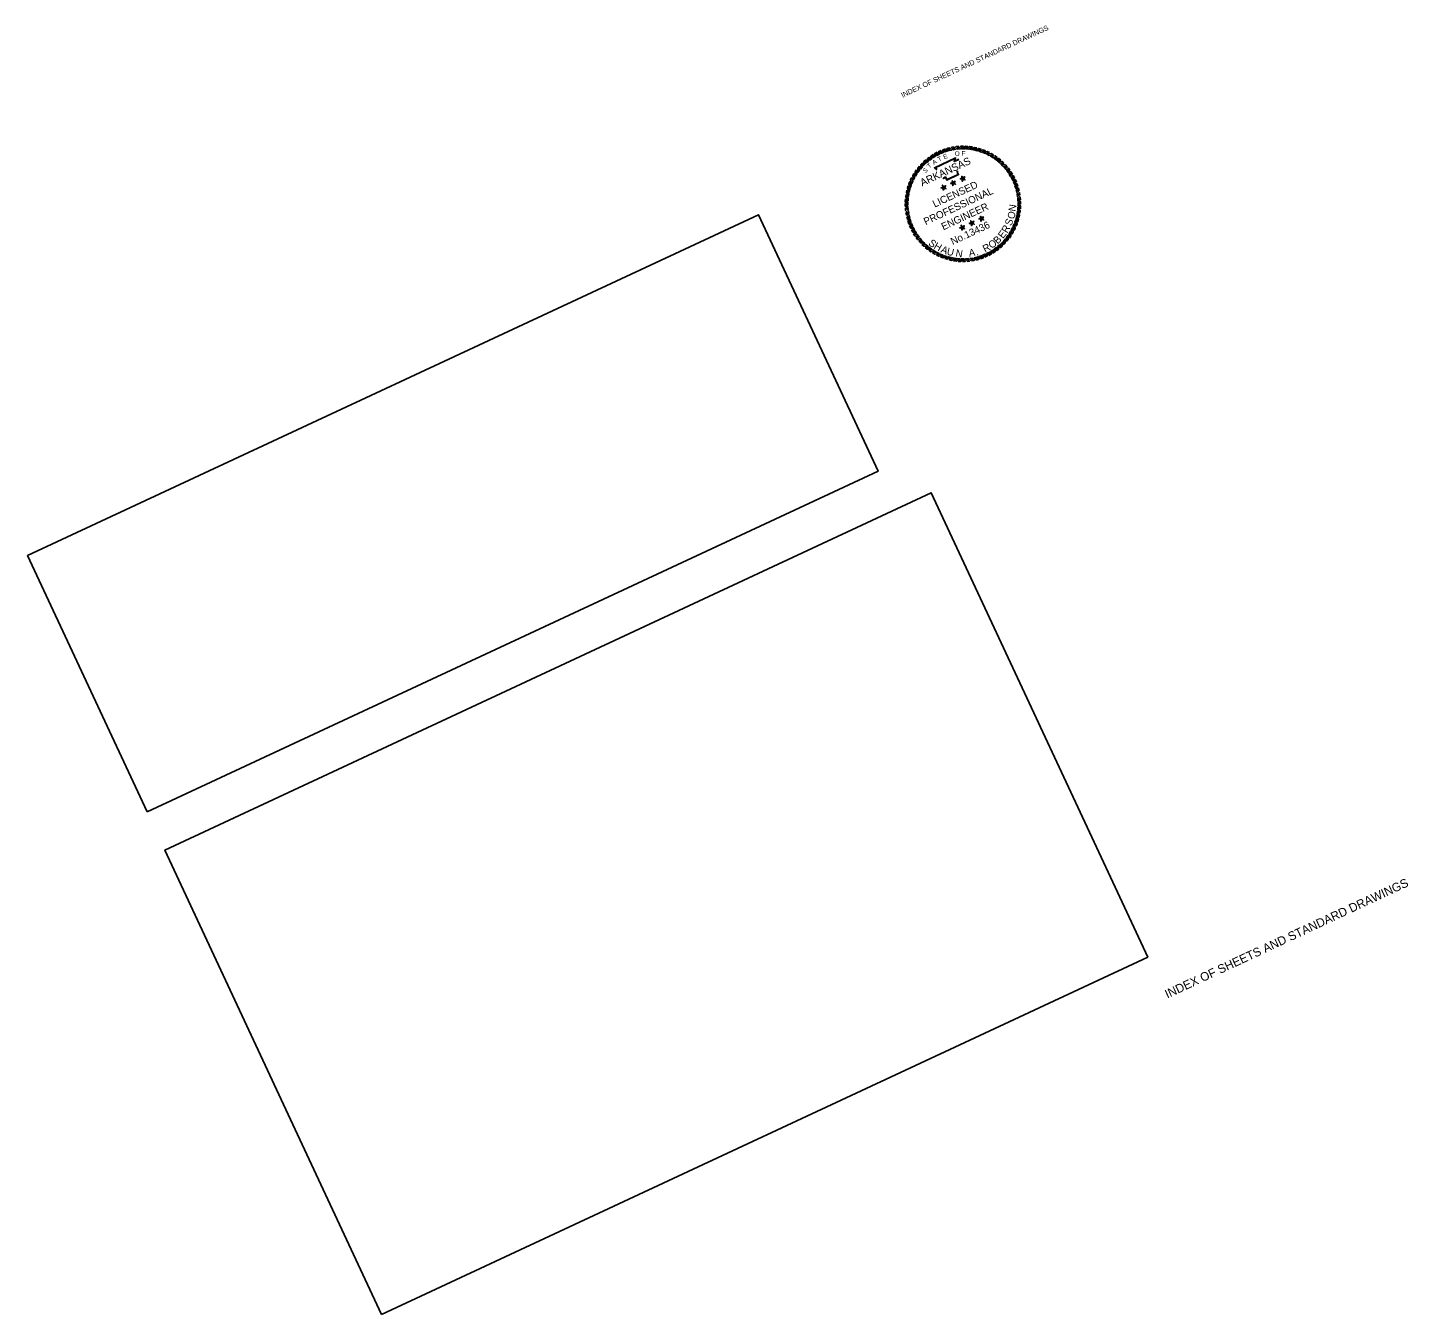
# Model space of a CAD drawing. Extents: x 757035 to 763666, y 1656342 to 1660766.
# Drawn here: x 757035 to 759892, y 1656342 to 1659005 of the extents above; entities that cross this region are included whole.
import ezdxf

# ---------------------------------------------------------------- set-up
doc = ezdxf.new("R2010")
doc.units = 0
for name, color, linetype in [('1', 7, 'Continuous'), ('60', 7, 'Continuous'), ('G-ANNO-SYMB', 7, 'Continuous')]:
    doc.layers.add(name, color=color, linetype=linetype)

msp = doc.modelspace()

# ---------------------------------------------------------------- linework, layer by layer
at = {"layer": '1'}
for points in [[(757282.5, 1657381.6), (758794.6, 1658086.7), (758547.2, 1658617.2), (757035.2, 1657912.1)], [(757767.2, 1656341.8), (759352.5, 1657081.1), (758904.4, 1658042), (757319.2, 1657302.7)]]:
    msp.add_lwpolyline(points, close=True, dxfattribs=at)
at = {"layer": 'G-ANNO-SYMB'}
for points in [[(758934, 1658753.5), (758929.1, 1658751.9), (758924.4, 1658744.1), (758929.5, 1658746.2)], [(758943, 1658756), (758938, 1658754.8), (758932.7, 1658747.4), (758938, 1658749.1)], [(758952.2, 1658757.8), (758947.2, 1658756.9), (758941.2, 1658750), (758946.6, 1658751.2)], [(758961.5, 1658758.8), (758956.4, 1658758.4), (758950, 1658751.9), (758955.4, 1658752.7)], [(758970.9, 1658759.2), (758965.8, 1658759.1), (758958.8, 1658753.1), (758964.3, 1658753.6)], [(758980.3, 1658758.7), (758975.1, 1658759.1), (758967.7, 1658753.7), (758973.3, 1658753.7)], [(758989.6, 1658757.6), (758984.5, 1658758.3), (758976.7, 1658753.5), (758982.2, 1658753.1)], [(758998.7, 1658755.7), (758993.7, 1658756.8), (758985.6, 1658752.7), (758991, 1658751.8)], [(759007.7, 1658753.1), (759002.8, 1658754.6), (758994.4, 1658751.1), (758999.8, 1658749.8)], [(758886.3, 1658724.7), (758882.7, 1658721.1), (758882, 1658711.9), (758885.6, 1658716.1)], [(758893.2, 1658731.1), (758889.4, 1658727.7), (758887.9, 1658718.6), (758891.9, 1658722.5)], [(758900.6, 1658736.8), (758896.5, 1658733.7), (758894.4, 1658724.8), (758898.6, 1658728.4)], [(758908.4, 1658742), (758904.1, 1658739.2), (758901.3, 1658730.5), (758905.8, 1658733.8)], [(758916.6, 1658746.5), (758912.1, 1658744.1), (758908.6, 1658735.6), (758913.3, 1658738.5)], [(758925.2, 1658750.4), (758920.5, 1658748.3), (758916.3, 1658740.2), (758921.3, 1658742.7)], [(759016.5, 1658749.8), (759011.7, 1658751.7), (759003, 1658748.9), (759008.3, 1658747.1)], [(759025, 1658745.8), (759020.4, 1658748.1), (759011.5, 1658745.9), (759016.6, 1658743.8)], [(759033.1, 1658741.2), (759028.7, 1658743.8), (759019.7, 1658742.4), (759024.6, 1658739.8)], [(759040.9, 1658735.9), (759036.7, 1658738.9), (759027.6, 1658738.2), (759032.3, 1658735.2)], [(759048.2, 1658730.1), (759044.3, 1658733.4), (759035.1, 1658733.4), (759039.6, 1658730.1)], [(759055, 1658723.7), (759051.4, 1658727.2), (759042.2, 1658728), (759046.4, 1658724.4)], [(758868.8, 1658702.8), (758866.2, 1658698.4), (758867.6, 1658689.4), (758870.1, 1658694.3)], [(758874.1, 1658710.6), (758871.1, 1658706.4), (758871.8, 1658697.3), (758874.7, 1658702)], [(758879.9, 1658717.9), (758876.6, 1658714), (758876.6, 1658704.8), (758879.9, 1658709.3)], [(758969.8, 1658692.1), (758970.2, 1658694.2), (758967.5, 1658697.1), (758968, 1658693.1)], [(758969.8, 1658692.1), (758971.9, 1658692.4), (758973.8, 1658695.8), (758970.2, 1658694.2)], [(759061.4, 1658716.8), (759058, 1658720.6), (759048.9, 1658722), (759052.8, 1658718.1)], [(759067.1, 1658709.4), (759064, 1658713.5), (759055.1, 1658715.6), (759058.7, 1658711.4)], [(759072.3, 1658701.5), (759069.5, 1658705.9), (759060.8, 1658708.7), (759064.1, 1658704.2)], [(759076.8, 1658693.3), (759074.4, 1658697.9), (759065.9, 1658701.4), (759068.8, 1658696.6)], [(758854.3, 1658668.4), (758853.2, 1658663.4), (758857.3, 1658655.3), (758858.2, 1658660.7)], [(758856.9, 1658677.4), (758855.4, 1658672.5), (758858.9, 1658664.1), (758860.2, 1658669.5)], [(758860.2, 1658686.2), (758858.3, 1658681.4), (758861.1, 1658672.7), (758862.9, 1658678)], [(758864.2, 1658694.7), (758861.9, 1658690.1), (758864, 1658681.2), (758866.2, 1658686.3)], [(758930.3, 1658673.7), (758928.5, 1658674.7), (758924.9, 1658673), (758928.8, 1658672.3)], [(758930.3, 1658673.7), (758930.7, 1658675.7), (758928, 1658678.6), (758928.5, 1658674.7)], [(758930.3, 1658673.7), (758928.8, 1658672.3), (758929.2, 1658668.3), (758931.2, 1658671.8)], [(758930.3, 1658673.7), (758932.4, 1658673.9), (758934.3, 1658677.4), (758930.7, 1658675.7)], [(758930.3, 1658673.7), (758931.2, 1658671.8), (758935.1, 1658671), (758932.4, 1658673.9)], [(758950.1, 1658682.9), (758948.2, 1658683.9), (758944.6, 1658682.2), (758948.5, 1658681.5)], [(758950.1, 1658682.9), (758950.5, 1658684.9), (758947.8, 1658687.8), (758948.2, 1658683.9)], [(758950.1, 1658682.9), (758948.5, 1658681.5), (758949, 1658677.5), (758950.9, 1658681)], [(758950.1, 1658682.9), (758952.1, 1658683.2), (758954, 1658686.6), (758950.5, 1658684.9)], [(758950.1, 1658682.9), (758950.9, 1658681), (758954.8, 1658680.3), (758952.1, 1658683.2)], [(758969.8, 1658692.1), (758968, 1658693.1), (758964.4, 1658691.5), (758968.3, 1658690.7)], [(758969.8, 1658692.1), (758968.3, 1658690.7), (758968.8, 1658686.8), (758970.7, 1658690.2)], [(758969.8, 1658692.1), (758970.7, 1658690.2), (758974.6, 1658689.5), (758971.9, 1658692.4)], [(759080.7, 1658684.8), (759078.6, 1658689.5), (759070.5, 1658693.7), (759073, 1658688.7)], [(759083.8, 1658676), (759082.2, 1658680.8), (759074.4, 1658685.6), (759076.5, 1658680.5)], [(759086.3, 1658667), (759085.1, 1658671.9), (759077.7, 1658677.3), (759079.4, 1658672)], [(759088.1, 1658657.8), (759087.2, 1658662.8), (759080.3, 1658668.8), (759081.5, 1658663.4)], [(758850.8, 1658640.6), (758850.9, 1658635.5), (758856.8, 1658628.5), (758856.4, 1658634)], [(758851.3, 1658650), (758850.9, 1658644.8), (758856.3, 1658637.4), (758856.3, 1658643)], [(758852.4, 1658659.2), (758851.7, 1658654.2), (758856.5, 1658646.4), (758856.9, 1658651.9)], [(759089.1, 1658648.4), (759088.7, 1658653.6), (759082.2, 1658660), (759083.1, 1658654.5)], [(759089.5, 1658639.1), (759089.4, 1658644.2), (759083.4, 1658651.2), (759083.9, 1658645.6)], [(759089, 1658629.7), (759089.4, 1658634.8), (759084, 1658642.2), (759084, 1658636.7)], [(758851.1, 1658631.2), (758851.6, 1658626.1), (758858.1, 1658619.7), (758857.2, 1658625.1)], [(758852.2, 1658621.9), (758853.1, 1658616.9), (758860, 1658610.9), (758858.7, 1658616.3)], [(758853.9, 1658612.7), (758855.2, 1658607.7), (758862.6, 1658602.4), (758860.9, 1658607.7)], [(759008.4, 1658609.3), (759006.6, 1658610.3), (759003, 1658608.7), (759006.9, 1658607.9)], [(759008.4, 1658609.3), (759008.8, 1658611.4), (759006.1, 1658614.3), (759006.6, 1658610.3)], [(759008.4, 1658609.3), (759006.9, 1658607.9), (759007.4, 1658604), (759009.3, 1658607.4)], [(759008.4, 1658609.3), (759010.5, 1658609.6), (759012.4, 1658613), (759008.8, 1658611.4)], [(759008.4, 1658609.3), (759009.3, 1658607.4), (759013.2, 1658606.7), (759010.5, 1658609.6)], [(759083.4, 1658602.3), (759084.9, 1658607.2), (759081.4, 1658615.6), (759080.1, 1658610.2)], [(759086, 1658611.3), (759087.1, 1658616.3), (759083, 1658624.4), (759082.1, 1658618.9)], [(759087.9, 1658620.4), (759088.6, 1658625.5), (759083.8, 1658633.3), (759083.4, 1658627.8)], [(758856.4, 1658603.7), (758858.1, 1658598.8), (758865.9, 1658594.1), (758863.8, 1658599.2)], [(758859.6, 1658594.9), (758861.7, 1658590.2), (758869.8, 1658586), (758867.3, 1658591)], [(758863.5, 1658586.3), (758865.9, 1658581.8), (758874.3, 1658578.3), (758871.5, 1658583)], [(758968.9, 1658590.9), (758967.1, 1658591.9), (758963.5, 1658590.2), (758967.4, 1658589.5)], [(758968.9, 1658590.9), (758969.3, 1658592.9), (758966.6, 1658595.8), (758967.1, 1658591.9)], [(758968.9, 1658590.9), (758967.4, 1658589.5), (758967.9, 1658585.5), (758969.8, 1658589)], [(758968.9, 1658590.9), (758971, 1658591.1), (758972.9, 1658594.6), (758969.3, 1658592.9)], [(758968.9, 1658590.9), (758969.8, 1658589), (758973.7, 1658588.2), (758971, 1658591.1)], [(758988.7, 1658600.1), (758986.9, 1658601.1), (758983.3, 1658599.4), (758987.1, 1658598.7)], [(758988.7, 1658600.1), (758989.1, 1658602.1), (758986.4, 1658605), (758986.9, 1658601.1)], [(758988.7, 1658600.1), (758987.1, 1658598.7), (758987.6, 1658594.7), (758989.6, 1658598.2)], [(758988.7, 1658600.1), (758990.7, 1658600.4), (758992.7, 1658603.8), (758989.1, 1658602.1)], [(758988.7, 1658600.1), (758989.6, 1658598.2), (758993.4, 1658597.5), (758990.7, 1658600.4)], [(759066.2, 1658569.1), (759069.2, 1658573.3), (759068.5, 1658582.4), (759065.5, 1658577.7)], [(759071.5, 1658576.9), (759074.1, 1658581.3), (759072.7, 1658590.3), (759070.1, 1658585.4)], [(759076.1, 1658585), (759078.4, 1658589.6), (759076.2, 1658598.5), (759074.1, 1658593.4)], [(759080.1, 1658593.5), (759082, 1658598.3), (759079.2, 1658606.9), (759077.4, 1658601.7)], [(758868, 1658578.1), (758870.8, 1658573.8), (758879.5, 1658571), (758876.2, 1658575.5)], [(758873.2, 1658570.3), (758876.2, 1658566.2), (758885.1, 1658564.1), (758881.6, 1658568.3)], [(758878.9, 1658562.9), (758882.3, 1658559.1), (758891.3, 1658557.6), (758887.4, 1658561.6)], [(758885.2, 1658556), (758888.9, 1658552.4), (758898, 1658551.7), (758893.8, 1658555.3)], [(759039.7, 1658542.9), (759043.8, 1658545.9), (759045.9, 1658554.8), (759041.7, 1658551.3)], [(759047.1, 1658548.6), (759050.9, 1658552), (759052.3, 1658561), (759048.4, 1658557.1)], [(759054, 1658554.9), (759057.5, 1658558.6), (759058.3, 1658567.7), (759054.7, 1658563.5)], [(759060.4, 1658561.8), (759063.7, 1658565.7), (759063.7, 1658574.9), (759060.4, 1658570.4)], [(758892.1, 1658549.6), (758896, 1658546.3), (758905.2, 1658546.3), (758900.7, 1658549.6)], [(758899.4, 1658543.8), (758903.6, 1658540.8), (758912.7, 1658541.5), (758908, 1658544.4)], [(758907.2, 1658538.5), (758911.6, 1658535.9), (758920.6, 1658537.3), (758915.7, 1658539.8)], [(758915.3, 1658533.9), (758919.9, 1658531.6), (758928.8, 1658533.7), (758923.7, 1658535.9)], [(758923.8, 1658529.9), (758928.6, 1658528), (758937.3, 1658530.8), (758932, 1658532.6)], [(758932.6, 1658526.6), (758937.5, 1658525.1), (758945.9, 1658528.6), (758940.5, 1658529.9)], [(758941.6, 1658524), (758946.6, 1658522.9), (758954.7, 1658527), (758949.2, 1658527.9)], [(758950.7, 1658522.1), (758955.8, 1658521.4), (758963.6, 1658526.2), (758958.1, 1658526.6)], [(758960, 1658520.9), (758965.1, 1658520.6), (758972.5, 1658526), (758967, 1658526)], [(758969.4, 1658520.5), (758974.5, 1658520.6), (758981.5, 1658526.5), (758975.9, 1658526.1)], [(758978.7, 1658520.8), (758983.9, 1658521.3), (758990.3, 1658527.8), (758984.8, 1658526.9)], [(758988.1, 1658521.9), (758993.1, 1658522.8), (758999.1, 1658529.7), (758993.7, 1658528.4)], [(758997.3, 1658523.6), (759002.2, 1658524.9), (759007.6, 1658532.3), (759002.3, 1658530.6)], [(759006.3, 1658526.1), (759011.1, 1658527.8), (759015.9, 1658535.6), (759010.8, 1658533.5)], [(759015.1, 1658529.3), (759019.8, 1658531.4), (759024, 1658539.5), (759019, 1658537)], [(759023.6, 1658533.2), (759028.2, 1658535.6), (759031.7, 1658544), (759026.9, 1658541.2)], [(759031.8, 1658537.7), (759036.2, 1658540.5), (759039, 1658549.2), (759034.5, 1658545.9)]]:
    msp.add_lwpolyline(points, close=True, dxfattribs=at)
for points in [[(758916.2, 1658710.2), (758911.2, 1658714.5), (758954.8, 1658734.9), (758953.2, 1658728.6), (758956.2, 1658730), (758958.7, 1658731.2), (758961.3, 1658732.1)], [(758916.7, 1658710.8), (758912.6, 1658714.3), (758953.6, 1658733.5), (758952.1, 1658727.2), (758956.5, 1658729.4), (758958.9, 1658730.5), (758961.5, 1658731.4)], [(758959, 1658707.9), (758958.5, 1658707), (758958.7, 1658706), (758959.5, 1658703.6), (758960.9, 1658700.6), (758936.5, 1658689.2), (758934.6, 1658693.3), (758934.2, 1658694.2), (758933.1, 1658694), (758929.6, 1658692.4), (758928.6, 1658693.1)], [(758958.3, 1658708.3), (758957.7, 1658707.1), (758957.9, 1658705.8), (758958.8, 1658703.3), (758959.9, 1658700.9), (758936.9, 1658690.2), (758935.3, 1658693.6), (758934.7, 1658695), (758932.9, 1658694.8), (758929.7, 1658693.3), (758929, 1658693.7)]]:
    msp.add_lwpolyline(points, dxfattribs=at)

# ---------------------------------------------------------------- texts
at = {"layer": '1'}
msp.add_text('INDEX OF SHEETS AND STANDARD DRAWINGS', height=10.552, rotation=25, dxfattribs=at).set_placement((758845.2, 1658859.3))
at = {"layer": '60'}
msp.add_text('INDEX OF SHEETS AND STANDARD DRAWINGS', height=18, rotation=25, dxfattribs=at).set_placement((759393, 1656995.3))
at = {"layer": 'G-ANNO-SYMB'}
for s, height, rotation, p in [('ARKANSAS', 15.49, 25, (758885.8, 1658675.7)), ('T', 9.49, 41.9015, (758900.8, 1658712.5)), ('A', 9.49, 33.6788, (758910, 1658720.1)), ('T', 9.49, 26.4789, (758920.3, 1658727)), ('E', 9.49, 21.672, (758931.4, 1658731.9)), ('O', 9.49, 6.2218, (758953.7, 1658738.7)), ('F', 9.49, 0.3628, (758967.4, 1658739.6)), ('S', 9.49, 44.7726, (758892.2, 1658702.5)), ('PROFESSIONAL', 15, 25, (758893, 1658595.6)), ('LICENSED', 15, 25, (758911.6, 1658631.9)), ('ENGINEER', 15, 25, (758929.5, 1658584.9)), ('N', 15, 81.1007, (759078.8, 1658623.3)), ('O', 15, 69.7757, (759075, 1658606.7)), ('No.13436', 14.94, 25, (758948.9, 1658554.5)), ('E', 15, 52.8315, (759053, 1658566.9)), ('R', 15, 60.6597, (759061.7, 1658578.2)), ('S', 15, 68.4878, (759069.9, 1658593.3)), ('S', 15, 323.1636, (758897.4, 1658556)), ('H', 15, 330.619, (758908.5, 1658548.3)), ('R', 15, 28.2287, (759015.8, 1658539)), ('O', 15, 36.4296, (759029.3, 1658546.3)), ('B', 15, 43.885, (759041.6, 1658555.6)), ('A', 15, 338.4472, (758923, 1658539.9)), ('U', 15, 345.9026, (758935.6, 1658535)), ('N', 15, 349.9326, (758954, 1658531.2)), ('A', 15, 8.0991, (758983.1, 1658530.6)), ('.', 15, 16.3, (758998.3, 1658532.9))]:
    msp.add_text(s, height=height, rotation=rotation, dxfattribs=at).set_placement(p)

doc.saveas('drawing.dxf')
